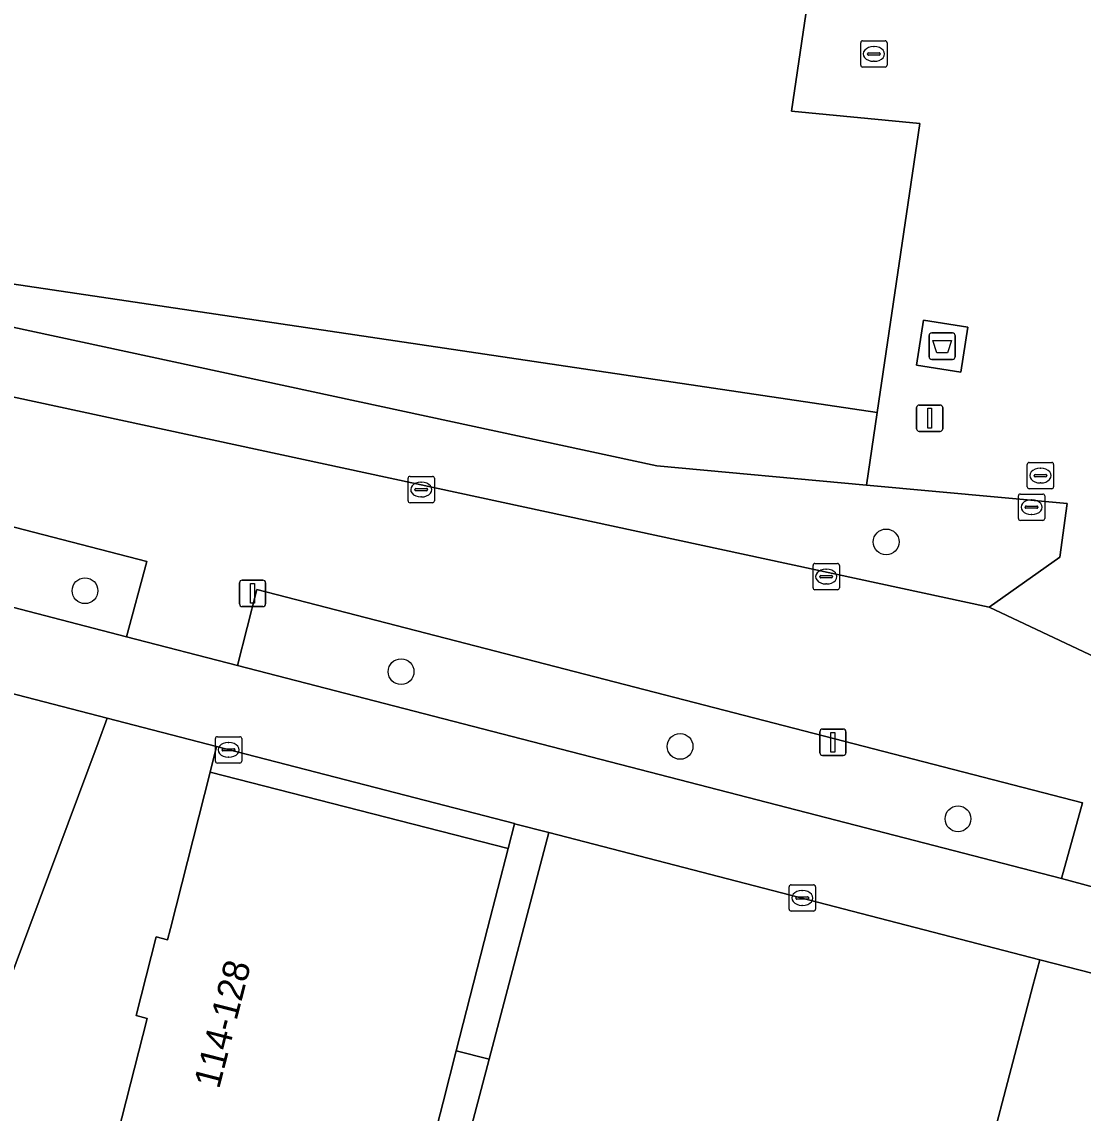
# Model space of a CAD drawing. Extents: x 163683 to 164494, y 382709 to 383872.
# Drawn here: x 164120.38 to 164160.65, y 383242.99 to 383284.39 of the extents above; entities that cross this region are included whole.
import ezdxf

# ---------------------------------------------------------------- set-up
doc = ezdxf.new("R2010")
doc.units = 0
for name, color, linetype in [('IMGEO_Afval_apart_plaats', 7, 'Continuous'), ('IMGEO_Boom', 7, 'Continuous'), ('IMGEO_Groenvoorziening', 7, 'Continuous'), ('IMGEO_Kolk', 7, 'Continuous'), ('IMGEO_Lichtmast', 7, 'Continuous'), ('IMGEO_Pand', 7, 'Continuous'), ('IMGEO_Pand_nummerreeks', 7, 'Continuous'), ('IMGEO_Rijbaan_lokaal_open', 7, 'Continuous'), ('IMGEO_Rioolput', 7, 'Continuous'), ('IMGEO_Voetpad_gesloten', 7, 'Continuous'), ('IMGEO_Voetpad_op_trap', 7, 'Continuous'), ('IMGEO_Voetpad_open', 7, 'Continuous')]:
    doc.layers.add(name, color=color, linetype=linetype)

msp = doc.modelspace()

# ---------------------------------------------------------------- linework, layer by layer
at = {"layer": 'IMGEO_Afval_apart_plaats'}
for p, q in [((164154.905, 383272.588), (164155.695, 383272.588)), ((164155.695, 383272.588), (164154.905, 383272.588)), ((164154.805, 383271.688), (164154.805, 383272.488)), ((164154.805, 383272.488), (164154.805, 383271.688)), ((164155.795, 383272.488), (164155.795, 383271.688)), ((164155.795, 383271.688), (164155.795, 383272.488)), ((164155.695, 383271.588), (164154.905, 383271.588)), ((164154.905, 383271.588), (164155.695, 383271.588))]:
    msp.add_line(p, q, dxfattribs=at)
msp.add_lwpolyline([(164154.948, 383272.302), (164155.652, 383272.302), (164155.503, 383271.832), (164155.097, 383271.832), (164154.948, 383272.302)], dxfattribs=at)
for centre, start, end in [((164154.905, 383272.488), 90, 180), ((164154.905, 383272.488), 90, 180), ((164155.695, 383272.488), 0, 90), ((164155.695, 383272.488), 360, 90), ((164154.905, 383271.688), 180, 270), ((164154.905, 383271.688), 180, 270), ((164155.695, 383271.688), 270, 0), ((164155.695, 383271.688), 270, 0)]:
    msp.add_arc(centre, 0.1, start, end, dxfattribs=at)
at = {"layer": 'IMGEO_Boom'}
for centre in [(164153.177, 383264.662), (164122.778, 383262.812), (164134.771, 383259.741), (164145.358, 383256.907), (164155.902, 383254.16)]:
    msp.add_circle(centre, 0.489, dxfattribs=at)
at = {"layer": 'IMGEO_Groenvoorziening'}
for points in [[(164104.165, 383276.221), (164097.05, 383278.083), (164100.264, 383290.889), (164096.377, 383291.894), (164092.452, 383276.624), (164104.87, 383273.428), (164157.09, 383262.182), (164159.765, 383264.084), (164160.049, 383266.117), (164152.429, 383266.819), (164144.47, 383267.553)], [(164125.123, 383263.925), (164085.439, 383274.191), (164084.726, 383271.367), (164124.347, 383261.058)], [(164120.646, 383250), (164123.272, 383257.038), (164123.622, 383257.976), (164096.288, 383265.053), (164094.222, 383256.527), (164090.371, 383240.637), (164088.728, 383241.035), (164087.976, 383238.019), (164090.482, 383237.371), (164092.518, 383236.844), (164113.599, 383231.393), (164114.133, 383232.549)], [(164160.62, 383254.762), (164129.301, 383262.861), (164128.56, 383259.97), (164159.824, 383251.896)], [(164127.773, 383256.901), (164127.524, 383255.923), (164138.83, 383253.031), (164139.075, 383253.975), (164139.072, 383253.976)], [(164158.743, 383247.827), (164159.002, 383248.816), (164144.135, 383252.665), (164140.374, 383253.639), (164138.11, 383245.043), (164133.916, 383229.12), (164132.78, 383229.418), (164132.029, 383226.485), (164134.512, 383225.831), (164136.533, 383225.298), (164139.444, 383224.531), (164151.761, 383221.285), (164151.842, 383221.557), (164152.167, 383222.743)]]:
    msp.add_lwpolyline(points, close=True, dxfattribs=at)
at = {"layer": 'IMGEO_Kolk'}
for p, q in [((164152.209, 383282.747), (164152.209, 383283.599)), ((164152.284, 383283.673), (164153.136, 383283.673)), ((164152.697, 383283.453), (164152.722, 383283.453)), ((164153.21, 383283.599), (164153.21, 383282.747)), ((164152.468, 383283.167), (164152.468, 383283.179)), ((164152.906, 383283.13), (164152.508, 383283.13)), ((164152.511, 383283.216), (164152.909, 383283.216)), ((164152.72, 383282.893), (164152.695, 383282.893)), ((164152.952, 383283.179), (164152.952, 383283.167)), ((164153.136, 383282.673), (164152.284, 383282.673)), ((164135.035, 383266.223), (164135.035, 383267.075)), ((164135.11, 383267.149), (164135.962, 383267.149)), ((164135.523, 383266.929), (164135.548, 383266.929)), ((164136.036, 383267.075), (164136.036, 383266.223)), ((164135.294, 383266.643), (164135.294, 383266.655)), ((164135.732, 383266.606), (164135.334, 383266.606)), ((164135.337, 383266.692), (164135.735, 383266.692)), ((164135.546, 383266.369), (164135.521, 383266.369)), ((164135.778, 383266.655), (164135.778, 383266.643)), ((164135.962, 383266.149), (164135.11, 383266.149)), ((164150.401, 383262.921), (164150.401, 383263.773)), ((164150.476, 383263.847), (164151.328, 383263.847)), ((164150.889, 383263.627), (164150.914, 383263.627)), ((164151.402, 383263.773), (164151.402, 383262.921)), ((164150.66, 383263.341), (164150.66, 383263.353)), ((164151.098, 383263.304), (164150.7, 383263.304)), ((164150.703, 383263.39), (164151.101, 383263.39)), ((164150.912, 383263.067), (164150.887, 383263.067)), ((164151.144, 383263.353), (164151.144, 383263.341)), ((164151.328, 383262.847), (164150.476, 383262.847)), ((164127.801, 383257.275), (164128.653, 383257.275)), ((164127.726, 383256.349), (164127.726, 383257.201)), ((164128.028, 383256.818), (164128.426, 383256.818)), ((164128.214, 383257.055), (164128.239, 383257.055)), ((164128.727, 383257.201), (164128.727, 383256.349)), ((164127.985, 383256.769), (164127.985, 383256.781)), ((164128.423, 383256.732), (164128.025, 383256.732)), ((164128.237, 383256.495), (164128.212, 383256.495)), ((164128.469, 383256.781), (164128.469, 383256.769)), ((164128.653, 383256.275), (164127.801, 383256.275)), ((164149.494, 383250.731), (164149.494, 383251.583)), ((164149.569, 383251.657), (164150.421, 383251.657)), ((164149.982, 383251.437), (164150.007, 383251.437)), ((164150.495, 383251.583), (164150.495, 383250.731)), ((164149.753, 383251.151), (164149.753, 383251.163)), ((164150.191, 383251.114), (164149.793, 383251.114)), ((164149.796, 383251.2), (164150.194, 383251.2)), ((164150.237, 383251.163), (164150.237, 383251.151)), ((164150.421, 383250.657), (164149.569, 383250.657)), ((164150.005, 383250.877), (164149.98, 383250.877))]:
    msp.add_line(p, q, dxfattribs=at)
for points in [[(164152.209, 383282.747), (164152.209, 383283.599)], [(164152.284, 383283.673), (164153.136, 383283.673)], [(164153.21, 383283.599), (164153.21, 383282.747)], [(164153.136, 383282.673), (164152.284, 383282.673)], [(164135.035, 383266.223), (164135.035, 383267.075)], [(164135.11, 383267.149), (164135.962, 383267.149)], [(164136.036, 383267.075), (164136.036, 383266.223)], [(164135.962, 383266.149), (164135.11, 383266.149)], [(164150.401, 383262.921), (164150.401, 383263.773)], [(164150.476, 383263.847), (164151.328, 383263.847)], [(164151.402, 383263.773), (164151.402, 383262.921)], [(164151.328, 383262.847), (164150.476, 383262.847)], [(164127.801, 383257.275), (164128.653, 383257.275)], [(164127.726, 383256.349), (164127.726, 383257.201)], [(164128.727, 383257.201), (164128.727, 383256.349)], [(164128.653, 383256.275), (164127.801, 383256.275)], [(164149.494, 383250.731), (164149.494, 383251.583)], [(164149.569, 383251.657), (164150.421, 383251.657)], [(164150.495, 383251.583), (164150.495, 383250.731)], [(164150.421, 383250.657), (164149.569, 383250.657)]]:
    msp.add_lwpolyline(points, dxfattribs=at)
for centre, radius, start, end in [((164152.286, 383283.597), 0.0765, 91.552, 178.448), ((164152.286, 383283.597), 0.0765, 91.552, 178.448), ((164153.134, 383283.597), 0.0765, 1.552, 88.448), ((164153.134, 383283.597), 0.0765, 1.552, 88.448), ((164152.508, 383283.176), 0.0403, 85.8775, 175.7526), ((164152.505, 383283.166), 0.0366, 178.938, 274.7102), ((164152.909, 383283.173), 0.043, 264.8664, 352.4533), ((164152.913, 383283.178), 0.0386, 1.7309, 96.639), ((164152.286, 383282.749), 0.0765, 181.552, 268.448), ((164152.286, 383282.749), 0.0765, 181.552, 268.448), ((164153.134, 383282.749), 0.0765, 271.552, 358.448), ((164153.134, 383282.749), 0.0765, 271.552, 358.448), ((164135.112, 383267.073), 0.0765, 91.552, 178.448), ((164135.112, 383267.073), 0.0765, 91.552, 178.448), ((164135.96, 383267.073), 0.0765, 1.552, 88.448), ((164135.96, 383267.073), 0.0765, 1.552, 88.448), ((164135.334, 383266.652), 0.0403, 85.8775, 175.7526), ((164135.331, 383266.642), 0.0366, 178.938, 274.7102), ((164135.735, 383266.649), 0.043, 264.8664, 352.4533), ((164135.739, 383266.654), 0.0386, 1.7309, 96.639), ((164135.112, 383266.225), 0.0765, 181.552, 268.448), ((164135.112, 383266.225), 0.0765, 181.552, 268.448), ((164135.96, 383266.225), 0.0765, 271.552, 358.448), ((164135.96, 383266.225), 0.0765, 271.552, 358.448), ((164150.478, 383263.771), 0.0765, 91.552, 178.448), ((164150.478, 383263.771), 0.0765, 91.552, 178.448), ((164151.326, 383263.771), 0.0765, 1.552, 88.448), ((164151.326, 383263.771), 0.0765, 1.552, 88.448), ((164150.7, 383263.35), 0.0403, 85.8775, 175.7526), ((164150.697, 383263.34), 0.0366, 178.938, 274.7102), ((164151.101, 383263.347), 0.043, 264.8664, 352.4533), ((164151.105, 383263.352), 0.0386, 1.7309, 96.639), ((164150.478, 383262.923), 0.0765, 181.552, 268.448), ((164150.478, 383262.923), 0.0765, 181.552, 268.448), ((164151.326, 383262.923), 0.0765, 271.552, 358.448), ((164151.326, 383262.923), 0.0765, 271.552, 358.448), ((164127.803, 383257.199), 0.0765, 91.552, 178.448), ((164127.803, 383257.199), 0.0765, 91.552, 178.448), ((164128.651, 383257.199), 0.0765, 1.552, 88.448), ((164128.651, 383257.199), 0.0765, 1.552, 88.448), ((164128.025, 383256.778), 0.0403, 85.8775, 175.7526), ((164128.43, 383256.78), 0.0386, 1.7309, 96.639), ((164128.022, 383256.768), 0.0366, 178.938, 274.7102), ((164128.426, 383256.775), 0.043, 264.8664, 352.4533), ((164127.803, 383256.351), 0.0765, 181.552, 268.448), ((164127.803, 383256.351), 0.0765, 181.552, 268.448), ((164128.651, 383256.351), 0.0765, 271.552, 358.448), ((164128.651, 383256.351), 0.0765, 271.552, 358.448), ((164149.571, 383251.581), 0.0765, 91.552, 178.448), ((164149.571, 383251.581), 0.0765, 91.552, 178.448), ((164150.419, 383251.581), 0.0765, 1.552, 88.448), ((164150.419, 383251.581), 0.0765, 1.552, 88.448), ((164149.793, 383251.16), 0.0403, 85.8775, 175.7526), ((164149.79, 383251.15), 0.0366, 178.938, 274.7102), ((164150.194, 383251.157), 0.043, 264.8664, 352.4533), ((164150.198, 383251.162), 0.0386, 1.7309, 96.639), ((164149.571, 383250.733), 0.0765, 181.552, 268.448), ((164149.571, 383250.733), 0.0765, 181.552, 268.448), ((164150.419, 383250.733), 0.0765, 271.552, 358.448), ((164150.419, 383250.733), 0.0765, 271.552, 358.448)]:
    msp.add_arc(centre, radius, start, end, dxfattribs=at)
for centre, major_axis, ratio, start_param, end_param in [((164152.696, 383283.173), (-0.387, 0.002), 0.722429, 4.712389, 7.853982), ((164152.721, 383283.173), (-0.39, 0.002), 0.717154, 1.570796, 4.712389), ((164135.522, 383266.649), (-0.387, 0.002), 0.722429, 4.712389, 7.853982), ((164135.547, 383266.649), (-0.39, 0.002), 0.717154, 1.570796, 4.712389), ((164150.888, 383263.347), (-0.387, 0.002), 0.722429, 4.712389, 7.853982), ((164150.913, 383263.347), (-0.39, 0.002), 0.717154, 1.570796, 4.712389), ((164128.213, 383256.775), (-0.387, 0.002), 0.722429, 4.712389, 7.853982), ((164128.238, 383256.775), (-0.39, 0.002), 0.717154, 1.570796, 4.712389), ((164149.981, 383251.157), (-0.387, 0.002), 0.722429, 4.712389, 7.853982), ((164150.006, 383251.157), (-0.39, 0.002), 0.717154, 1.570796, 4.712389)]:
    msp.add_ellipse(centre, major_axis=major_axis, ratio=ratio, start_param=start_param, end_param=end_param, dxfattribs=at)
at = {"layer": 'IMGEO_Lichtmast'}
for p, q in [((164154.331, 383268.956), (164154.331, 383269.756)), ((164154.331, 383269.756), (164154.331, 383268.956)), ((164154.431, 383269.856), (164155.221, 383269.856)), ((164155.221, 383269.856), (164154.431, 383269.856)), ((164155.321, 383269.756), (164155.321, 383268.956)), ((164155.321, 383268.956), (164155.321, 383269.756)), ((164155.221, 383268.856), (164154.431, 383268.856)), ((164154.431, 383268.856), (164155.221, 383268.856)), ((164128.64, 383262.311), (164128.64, 383263.111)), ((164128.64, 383263.111), (164128.64, 383262.311)), ((164128.74, 383263.211), (164129.53, 383263.211)), ((164129.53, 383263.211), (164128.74, 383263.211)), ((164129.63, 383263.111), (164129.63, 383262.311)), ((164129.63, 383262.311), (164129.63, 383263.111)), ((164129.53, 383262.211), (164128.74, 383262.211)), ((164128.74, 383262.211), (164129.53, 383262.211)), ((164150.66, 383256.664), (164150.66, 383257.464)), ((164150.66, 383257.464), (164150.66, 383256.664)), ((164150.76, 383257.564), (164151.55, 383257.564)), ((164151.55, 383257.564), (164150.76, 383257.564)), ((164151.65, 383257.464), (164151.65, 383256.664)), ((164151.65, 383256.664), (164151.65, 383257.464)), ((164151.55, 383256.564), (164150.76, 383256.564)), ((164150.76, 383256.564), (164151.55, 383256.564))]:
    msp.add_line(p, q, dxfattribs=at)
for points in [[(164154.751, 383269.731), (164154.901, 383269.731), (164154.901, 383268.981), (164154.751, 383268.981), (164154.751, 383269.731)], [(164129.06, 383263.086), (164129.21, 383263.086), (164129.21, 383262.336), (164129.06, 383262.336), (164129.06, 383263.086)], [(164151.08, 383257.439), (164151.23, 383257.439), (164151.23, 383256.689), (164151.08, 383256.689), (164151.08, 383257.439)]]:
    msp.add_lwpolyline(points, dxfattribs=at)
for centre, start, end in [((164154.431, 383269.756), 90, 180), ((164154.431, 383269.756), 90, 180), ((164155.221, 383269.756), 0, 90), ((164155.221, 383269.756), 360, 90), ((164154.431, 383268.956), 180, 270), ((164154.431, 383268.956), 180, 270), ((164155.221, 383268.956), 270, 0), ((164155.221, 383268.956), 270, 0), ((164128.74, 383263.111), 90, 180), ((164128.74, 383263.111), 90, 180), ((164129.53, 383263.111), 0, 90), ((164129.53, 383263.111), 360, 90), ((164128.74, 383262.311), 180, 270), ((164128.74, 383262.311), 180, 270), ((164129.53, 383262.311), 270, 0), ((164129.53, 383262.311), 270, 0), ((164150.76, 383257.464), 90, 180), ((164150.76, 383257.464), 90, 180), ((164151.55, 383257.464), 0, 90), ((164151.55, 383257.464), 360, 90), ((164150.76, 383256.664), 180, 270), ((164150.76, 383256.664), 180, 270), ((164151.55, 383256.664), 270, 0), ((164151.55, 383256.664), 270, 0)]:
    msp.add_arc(centre, 0.1, start, end, dxfattribs=at)
at = {"layer": 'IMGEO_Pand'}
msp.add_lwpolyline([(164106.517, 383295.769), (164105.106, 383276.669), (164152.837, 383269.576), (164154.457, 383280.534), (164149.581, 383281.003), (164150.192, 383285.109)], dxfattribs=at)
msp.add_lwpolyline([(164134.838, 383237.451), (164136.365, 383243.413), (164136.865, 383245.361), (164138.053, 383250), (164138.83, 383253.031), (164127.524, 383255.923), (164126.017, 383250), (164125.909, 383249.575), (164125.484, 383249.684), (164124.721, 383246.699), (164125.143, 383246.591), (164123.544, 383240.339)], close=True, dxfattribs=at)
at = {"layer": 'IMGEO_Rijbaan_lokaal_open'}
for points in [[(164271.701, 383222.816), (164268.729, 383223.586), (164261.081, 383225.568), (164257.211, 383226.591), (164216.897, 383237.018), (164213.023, 383237.975), (164172.813, 383248.485), (164168.945, 383249.5), (164163.294, 383250.964), (164159.824, 383251.896), (164128.56, 383259.97), (164124.347, 383261.058), (164084.726, 383271.367)], [(164083.709, 383268.31), (164094.904, 383265.411), (164096.288, 383265.053), (164123.622, 383257.976), (164127.773, 383256.901), (164139.072, 383253.976), (164139.075, 383253.975), (164140.374, 383253.639), (164144.135, 383252.665), (164159.002, 383248.816), (164162.51, 383247.908)]]:
    msp.add_lwpolyline(points, dxfattribs=at)
at = {"layer": 'IMGEO_Rioolput'}
for p, q in [((164158.53, 383266.752), (164158.53, 383267.604)), ((164158.605, 383267.678), (164159.457, 383267.678)), ((164159.531, 383267.604), (164159.531, 383266.752)), ((164158.789, 383267.172), (164158.789, 383267.184)), ((164158.832, 383267.221), (164159.23, 383267.221)), ((164159.018, 383267.458), (164159.043, 383267.458)), ((164159.273, 383267.184), (164159.273, 383267.172)), ((164159.227, 383267.135), (164158.829, 383267.135)), ((164159.041, 383266.898), (164159.016, 383266.898)), ((164158.193, 383265.554), (164158.193, 383266.406)), ((164158.268, 383266.48), (164159.12, 383266.48)), ((164159.457, 383266.678), (164158.605, 383266.678)), ((164159.194, 383266.406), (164159.194, 383265.554)), ((164158.452, 383265.974), (164158.452, 383265.986)), ((164158.89, 383265.937), (164158.492, 383265.937)), ((164158.495, 383266.023), (164158.893, 383266.023)), ((164158.681, 383266.26), (164158.706, 383266.26)), ((164158.936, 383265.986), (164158.936, 383265.974)), ((164158.704, 383265.7), (164158.679, 383265.7)), ((164159.12, 383265.48), (164158.268, 383265.48))]:
    msp.add_line(p, q, dxfattribs=at)
for points in [[(164158.53, 383266.752), (164158.53, 383267.604)], [(164158.605, 383267.678), (164159.457, 383267.678)], [(164159.531, 383267.604), (164159.531, 383266.752)], [(164158.193, 383265.554), (164158.193, 383266.406)], [(164158.268, 383266.48), (164159.12, 383266.48)], [(164159.457, 383266.678), (164158.605, 383266.678)], [(164159.194, 383266.406), (164159.194, 383265.554)], [(164159.12, 383265.48), (164158.268, 383265.48)]]:
    msp.add_lwpolyline(points, dxfattribs=at)
for centre, radius, start, end in [((164158.607, 383267.602), 0.0765, 91.552, 178.448), ((164158.607, 383267.602), 0.0765, 91.552, 178.448), ((164159.455, 383267.602), 0.0765, 1.552, 88.448), ((164159.455, 383267.602), 0.0765, 1.552, 88.448), ((164158.829, 383267.181), 0.0403, 85.8775, 175.7526), ((164158.826, 383267.171), 0.0366, 178.938, 274.7102), ((164159.23, 383267.178), 0.043, 264.8664, 352.4533), ((164159.234, 383267.183), 0.0386, 1.7309, 96.639), ((164158.607, 383266.754), 0.0765, 181.552, 268.448), ((164158.607, 383266.754), 0.0765, 181.552, 268.448), ((164159.455, 383266.754), 0.0765, 271.552, 358.448), ((164159.455, 383266.754), 0.0765, 271.552, 358.448), ((164158.27, 383266.404), 0.0765, 91.552, 178.448), ((164158.27, 383266.404), 0.0765, 91.552, 178.448), ((164159.118, 383266.404), 0.0765, 1.552, 88.448), ((164159.118, 383266.404), 0.0765, 1.552, 88.448), ((164158.492, 383265.983), 0.0403, 85.8775, 175.7526), ((164158.489, 383265.973), 0.0366, 178.938, 274.7102), ((164158.893, 383265.98), 0.043, 264.8664, 352.4533), ((164158.897, 383265.985), 0.0386, 1.7309, 96.639), ((164158.27, 383265.556), 0.0765, 181.552, 268.448), ((164158.27, 383265.556), 0.0765, 181.552, 268.448), ((164159.118, 383265.556), 0.0765, 271.552, 358.448), ((164159.118, 383265.556), 0.0765, 271.552, 358.448)]:
    msp.add_arc(centre, radius, start, end, dxfattribs=at)
for centre, major_axis, ratio, start_param, end_param in [((164159.017, 383267.178), (-0.387, 0.002), 0.722429, 4.712389, 7.853982), ((164159.042, 383267.178), (-0.39, 0.002), 0.717154, 1.570796, 4.712389), ((164158.68, 383265.98), (-0.387, 0.002), 0.722429, 4.712389, 7.853982), ((164158.705, 383265.98), (-0.39, 0.002), 0.717154, 1.570796, 4.712389)]:
    msp.add_ellipse(centre, major_axis=major_axis, ratio=ratio, start_param=start_param, end_param=end_param, dxfattribs=at)
at = {"layer": 'IMGEO_Voetpad_gesloten'}
msp.add_lwpolyline([(164156.279, 383272.81), (164154.59, 383273.076), (164154.321, 383271.366), (164156.009, 383271.1)], close=True, dxfattribs=at)
at = {"layer": 'IMGEO_Voetpad_op_trap'}
msp.add_lwpolyline([(164140.374, 383253.639), (164139.075, 383253.975), (164138.83, 383253.031), (164138.053, 383250), (164136.865, 383245.361), (164138.11, 383245.043)], close=True, dxfattribs=at)
at = {"layer": 'IMGEO_Voetpad_open'}
for points in [[(164167.597, 383257.227), (164157.09, 383262.182), (164104.87, 383273.428), (164092.452, 383276.624), (164096.377, 383291.894), (164100.264, 383290.889), (164105.146, 383289.627), (164104.165, 383276.221), (164144.47, 383267.553), (164152.429, 383266.819), (164152.837, 383269.576), (164105.106, 383276.669), (164106.517, 383295.769), (164087.253, 383300.767), (164083.28, 383301.798), (164076.416, 383275.682), (164069.907, 383273.328), (164068.019, 383272.649), (164066.67, 383272.184), (164065.393, 383272.51), (164066.402, 383269.822), (164066.728, 383269.996)], [(164082.321, 383271.854), (164084.726, 383271.367), (164085.439, 383274.191), (164125.123, 383263.925), (164124.347, 383261.058), (164128.56, 383259.97), (164129.301, 383262.861), (164160.62, 383254.762), (164159.824, 383251.896), (164163.294, 383250.964)], [(164123.544, 383240.339), (164125.143, 383246.591), (164124.721, 383246.699), (164125.484, 383249.684), (164125.909, 383249.575), (164126.017, 383250), (164127.524, 383255.923), (164127.773, 383256.901), (164123.622, 383257.976), (164123.272, 383257.038), (164120.646, 383250), (164114.133, 383232.549)]]:
    msp.add_lwpolyline(points, dxfattribs=at)
for points in [[(164172.045, 383287.201), (164172.791, 383287.15), (164170.869, 383289.667), (164161.895, 383287.693), (164154.459, 383286.101), (164150.192, 383285.109), (164149.581, 383281.003), (164154.457, 383280.534), (164152.837, 383269.576), (164152.429, 383266.819), (164160.049, 383266.117), (164159.765, 383264.084), (164157.09, 383262.182), (164167.597, 383257.227), (164169.075, 383267.189)], [(164156.279, 383272.81), (164156.009, 383271.1), (164154.321, 383271.366), (164154.59, 383273.076)], [(164160.833, 383241.512), (164162.249, 383246.911), (164162.51, 383247.908), (164159.002, 383248.816), (164158.743, 383247.827), (164152.167, 383222.743), (164151.842, 383221.557), (164155.374, 383220.693)], [(164138.11, 383245.043), (164136.865, 383245.361), (164136.365, 383243.413), (164134.838, 383237.451), (164133.31, 383231.488), (164132.78, 383229.418), (164133.916, 383229.12)]]:
    msp.add_lwpolyline(points, close=True, dxfattribs=at)

# ---------------------------------------------------------------- texts
at = {"layer": 'IMGEO_Pand_nummerreeks'}
msp.add_text('114-128', height=1, rotation=75.689, dxfattribs=at).set_placement((164127.865, 383243.882))

doc.saveas('drawing.dxf')
